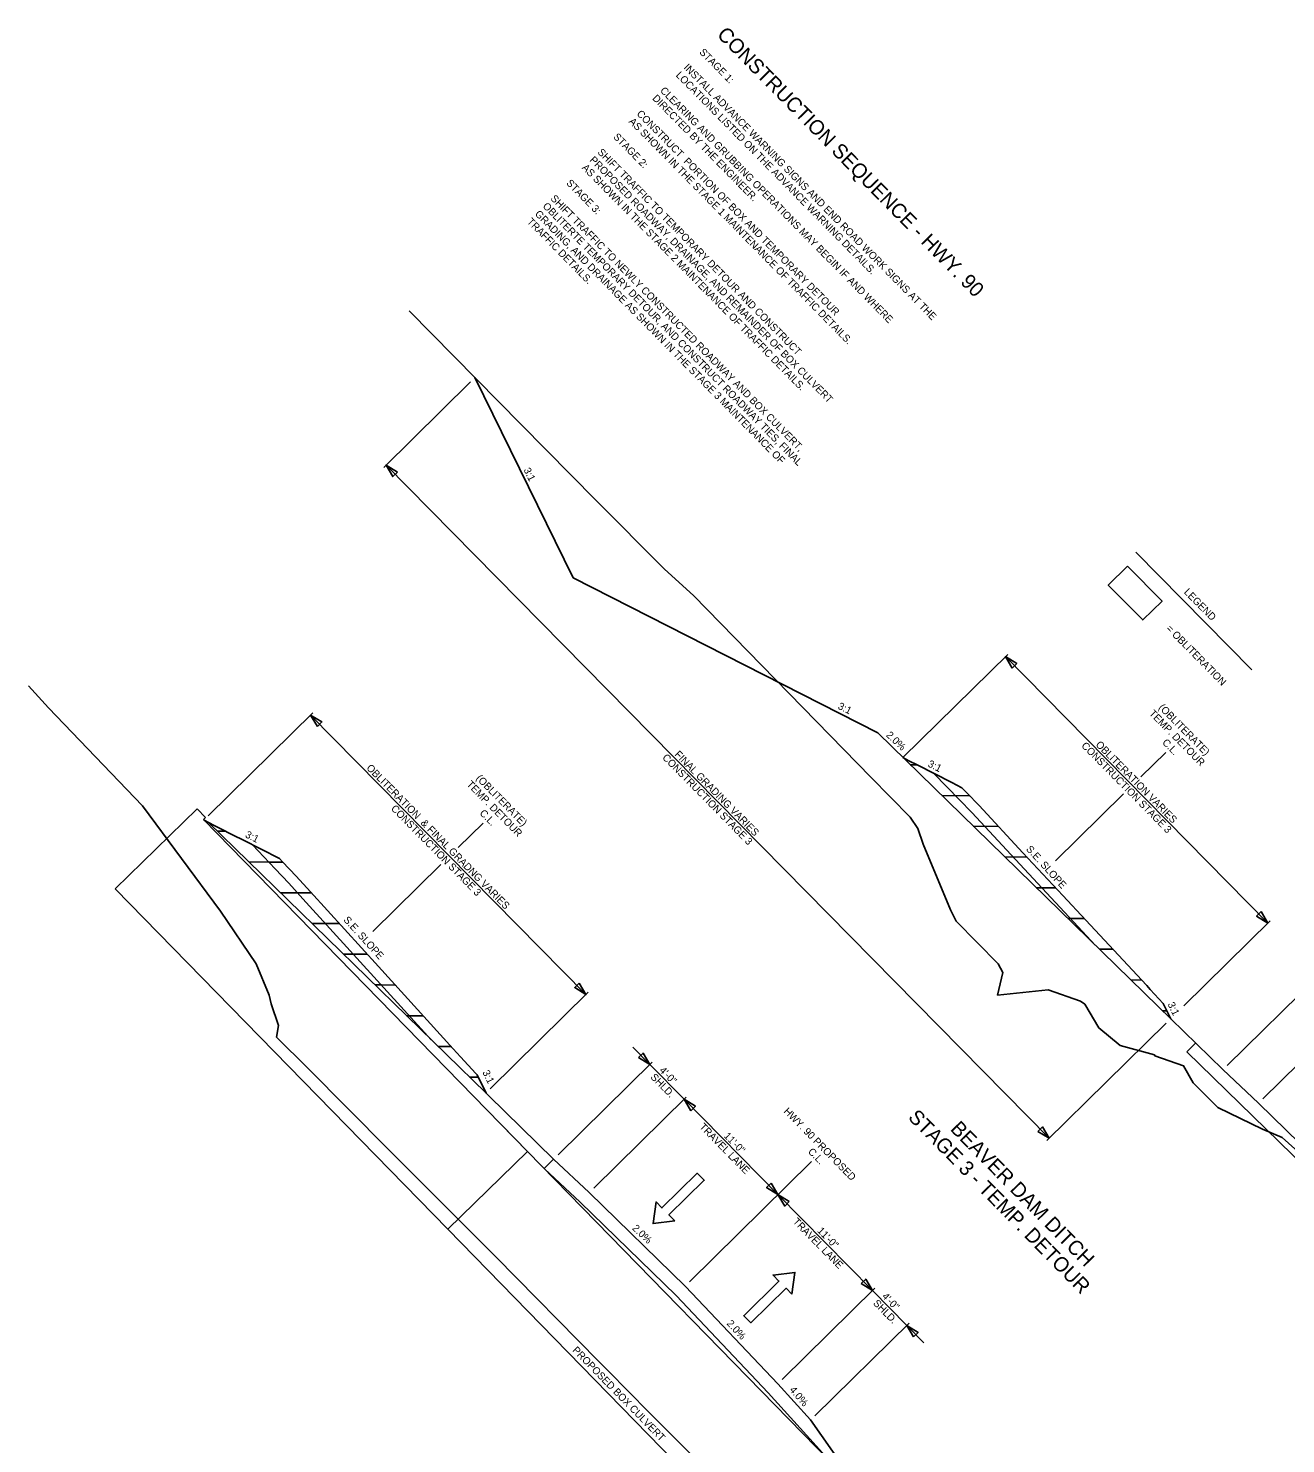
# Model space of a CAD drawing. Extents: x 1660305 to 1660468, y 670370 to 670550.
# Drawn here: x 1660305.5 to 1660408.5, y 670434.3 to 670550.3 of the extents above; entities that cross this region are included whole.
import ezdxf

# ---------------------------------------------------------------- set-up
doc = ezdxf.new("R2010")
doc.units = 0
for name, color, linetype in [('Default', 7, 'Continuous'), ('R_Annotation', 7, 'Continuous'), ('R_Axis', 7, 'Continuous'), ('R_Dimension', 7, 'Continuous'), ('R_Exist Surface', 7, 'Continuous'), ('R_Fin Surface', 7, 'Continuous'), ('R_Horz Alg', 7, 'Continuous'), ('R_MOT', 7, 'Continuous')]:
    doc.layers.add(name, color=color, linetype=linetype)

msp = doc.modelspace()

# ---------------------------------------------------------------- linework, layer by layer
at = {"layer": 'Default'}
for points in [[(1660358.47, 670452.53), (1660356.68, 670452.31), (1660356.92, 670454.09), (1660357.4, 670453.6), (1660360.29, 670456.44), (1660360.87, 670455.86), (1660357.98, 670453.02)], [(1660368.05, 670446.53), (1660368.29, 670448.31), (1660366.51, 670448.09), (1660366.99, 670447.6), (1660364.11, 670444.76), (1660364.68, 670444.18), (1660367.57, 670447.02)]]:
    msp.add_lwpolyline(points, close=True, dxfattribs=at)
at = {"layer": 'R_Annotation'}
msp.add_line((1660396.23, 670507.34), (1660405.73, 670497.69), dxfattribs=at)
at = {"layer": 'R_Axis'}
msp.add_lwpolyline([(1660395.55, 670506.2), (1660398.37, 670503.33), (1660396.79, 670501.78), (1660393.97, 670504.64)], close=True, dxfattribs=at)
at = {"layer": 'R_Dimension'}
for p, q in [((1660341.73, 670521.29), (1660334.61, 670514.28)), ((1660334.8, 670514.47), (1660389.12, 670459.3)), ((1660377.14, 670490.51), (1660385.73, 670498.96)), ((1660385.54, 670498.78), (1660407.04, 670476.94)), ((1660320.24, 670485.73), (1660328.81, 670494.18)), ((1660328.62, 670493.99), (1660351.18, 670471.08)), ((1660400.16, 670470.17), (1660407.23, 670477.13)), ((1660403.71, 670465.28), (1660411.42, 670472.87)), ((1660343.34, 670463.36), (1660351.37, 670471.27)), ((1660406.63, 670462.54), (1660414.22, 670470.02)), ((1660398.72, 670468.75), (1660388.93, 670459.11)), ((1660356.41, 670465.35), (1660355.01, 670466.77)), ((1660348.89, 670457.95), (1660356.6, 670465.53)), ((1660359.22, 670462.5), (1660356.41, 670465.35)), ((1660351.81, 670455.21), (1660359.4, 670462.68)), ((1660351.81, 670455.21), (1660359.4, 670462.68)), ((1660359.22, 670462.5), (1660366.9, 670454.69)), ((1660374.65, 670446.82), (1660366.9, 670454.69)), ((1660367.25, 670439.53), (1660374.84, 670447.01)), ((1660374.65, 670446.82), (1660377.46, 670443.97)), ((1660369.94, 670436.57), (1660377.65, 670444.16)), ((1660377.46, 670443.97), (1660378.86, 670442.55))]:
    msp.add_line(p, q, dxfattribs=at)
for points in [[(1660335.73, 670513.9), (1660334.8, 670514.47), (1660335.35, 670513.53)], [(1660386.09, 670497.84), (1660385.54, 670498.78), (1660386.47, 670498.21)], [(1660329.18, 670493.05), (1660328.62, 670493.99), (1660329.55, 670493.42)], [(1660406.49, 670477.88), (1660407.04, 670476.94), (1660406.11, 670477.51)], [(1660350.63, 670472.02), (1660351.18, 670471.08), (1660350.26, 670471.65)], [(1660355.48, 670465.92), (1660356.41, 670465.35), (1660355.86, 670466.29)], [(1660359.77, 670461.56), (1660359.22, 670462.5), (1660360.14, 670461.93)], [(1660388.19, 670459.87), (1660389.12, 670459.3), (1660388.57, 670460.24)], [(1660366.35, 670455.63), (1660366.9, 670454.69), (1660365.97, 670455.26)], [(1660367.83, 670454.12), (1660366.9, 670454.69), (1660367.46, 670453.75)], [(1660373.72, 670447.39), (1660374.65, 670446.82), (1660374.1, 670447.76)], [(1660378.01, 670443.03), (1660377.46, 670443.97), (1660378.39, 670443.4)]]:
    msp.add_lwpolyline(points, close=True, dxfattribs=at)
at = {"layer": 'R_Exist Surface'}
for points in [[(1660336.7, 670527.11), (1660345.87, 670517.8), (1660351.98, 670511.6), (1660357.62, 670505.95), (1660359.99, 670503.8), (1660374.51, 670488.91), (1660377.74, 670485.63), (1660378.37, 670484.7), (1660378.81, 670483.4), (1660381.03, 670478.03), (1660381.5, 670477.1), (1660384.96, 670473.59), (1660385.33, 670472.88), (1660384.9, 670471.04), (1660389.03, 670471.46), (1660391.7, 670470.54), (1660392.05, 670470.29), (1660393.2, 670468.35), (1660394.93, 670466.91), (1660397.74, 670466.13), (1660397.79, 670466.07), (1660400.14, 670465.23), (1660400.93, 670463.86), (1660402.93, 670461.82), (1660406.6, 670460.04), (1660408.22, 670459.37), (1660414.98, 670453.31)], [(1660305.5, 670496.38), (1660307.16, 670494.59), (1660314.86, 670486.54), (1660321.25, 670477.93), (1660324.15, 670473.59), (1660325.23, 670471.03), (1660325.39, 670470.33), (1660326, 670468.55), (1660325.84, 670467.6), (1660328.38, 670465.04), (1660334.97, 670458.4), (1660339.75, 670453.64), (1660343.8, 670449.59), (1660352.23, 670441.02), (1660352.99, 670440.24), (1660356.34, 670436.86), (1660362.34, 670430.84)]]:
    msp.add_lwpolyline(points, dxfattribs=at)
at = {"layer": 'R_Fin Surface'}
for points in [[(1660342.08, 670521.64), (1660350.13, 670505.24), (1660375.08, 670492.52), (1660398.05, 670470.11), (1660399.08, 670469.1)], [(1660319.89, 670485.37), (1660320.26, 670485.19), (1660342.99, 670463.01)]]:
    msp.add_lwpolyline(points, dxfattribs=at)
at = {"layer": 'R_Horz Alg'}
for p, q in [((1660396.64, 670488.93), (1660398.67, 670490.93)), ((1660389.65, 670482.04), (1660395.21, 670487.53)), ((1660340.72, 670483.13), (1660342.75, 670485.13)), ((1660333.73, 670476.25), (1660339.29, 670481.73)), ((1660359.66, 670447.55), (1660369.65, 670457.39))]:
    msp.add_line(p, q, dxfattribs=at)
at = {"layer": 'R_MOT'}
for p, q in [((1660377.74, 670489.92), (1660378.29, 670489.92)), ((1660381.77, 670487.04), (1660379.67, 670489.21)), ((1660380.33, 670487.4), (1660382.6, 670487.38)), ((1660382.78, 670486), (1660381.77, 670487.04)), ((1660319.32, 670486.31), (1660312.61, 670479.76)), ((1660319.32, 670486.31), (1660320.02, 670485.6)), ((1660386.36, 670482.15), (1660382.78, 670486)), ((1660320.02, 670485.6), (1660319.84, 670485.42)), ((1660319.84, 670485.42), (1660346.39, 670458.23)), ((1660320.99, 670484.47), (1660321.67, 670484.47)), ((1660382.91, 670484.88), (1660384.97, 670484.86)), ((1660385.49, 670482.36), (1660387.31, 670482.35)), ((1660389.63, 670478.64), (1660386.36, 670482.15)), ((1660323.57, 670481.95), (1660325.2, 670481.94)), ((1660325.19, 670481.94), (1660326.34, 670481.93)), ((1660388.07, 670479.84), (1660389.66, 670479.83)), ((1660312.61, 670479.76), (1660339.86, 670451.86)), ((1660326.15, 670479.43), (1660327.54, 670479.42)), ((1660327.54, 670479.42), (1660328.67, 670479.41)), ((1660391.51, 670476.62), (1660389.63, 670478.64)), ((1660328.74, 670476.91), (1660329.83, 670476.9)), ((1660329.83, 670476.91), (1660330.97, 670476.9)), ((1660390.66, 670477.32), (1660392.01, 670477.31)), ((1660392.89, 670475.14), (1660391.51, 670476.62)), ((1660331.32, 670474.39), (1660332.13, 670474.39)), ((1660332.12, 670474.39), (1660333.26, 670474.38)), ((1660393.24, 670474.8), (1660394.36, 670474.79)), ((1660333.9, 670471.87), (1660334.42, 670471.87)), ((1660334.42, 670471.87), (1660335.55, 670471.86)), ((1660395.82, 670472.28), (1660396.71, 670472.27)), ((1660398.41, 670469.76), (1660398.76, 670469.76)), ((1660336.48, 670469.35), (1660336.71, 670469.35)), ((1660336.71, 670469.35), (1660337.84, 670469.34)), ((1660400.41, 670466.4), (1660401.12, 670467.11)), ((1660339.06, 670466.83), (1660340.14, 670466.83)), ((1660341.65, 670464.31), (1660342.35, 670464.31)), ((1660344.26, 670460.41), (1660347.52, 670457.07)), ((1660346.39, 670458.23), (1660339.86, 670451.86)), ((1660374.3, 670429.64), (1660346.39, 670458.23)), ((1660348.53, 670457.59), (1660347.76, 670456.83)), ((1660339.86, 670451.86), (1660368.5, 670422.52))]:
    msp.add_line(p, q, dxfattribs=at)
for points in [[(1660377.14, 670490.51), (1660377.63, 670490.25), (1660378.3, 670489.91), (1660381.14, 670488.45), (1660381.98, 670488.02), (1660382.37, 670487.62), (1660383.38, 670486.58), (1660386.97, 670482.71), (1660390.24, 670479.21), (1660392.12, 670477.18), (1660397.11, 670471.85), (1660397.13, 670471.82), (1660397.41, 670471.51), (1660398.46, 670470.35), (1660398.58, 670470.12), (1660399.08, 670469.1)], [(1660319.88, 670485.38), (1660322.33, 670484.13), (1660323.07, 670483.75), (1660326.06, 670482.23), (1660326.31, 670481.96), (1660327.44, 670480.78), (1660328.6, 670479.49), (1660334.17, 670473.37), (1660340.31, 670466.64), (1660340.91, 670465.97), (1660342.15, 670464.61), (1660342.26, 670464.49), (1660342.99, 670463.01)], [(1660323.85, 670483.36), (1660325.71, 670481.39), (1660326.83, 670480.21), (1660327.98, 670478.93), (1660338.51, 670467.37)], [(1660323.85, 670483.36), (1660325.71, 670481.39), (1660326.83, 670480.21), (1660327.98, 670478.93), (1660338.51, 670467.37)], [(1660399.08, 670469.1), (1660403.35, 670464.93), (1660406.27, 670462.19), (1660414.15, 670454.51), (1660421.71, 670446.52), (1660424.4, 670443.56), (1660428.72, 670437.41), (1660429.07, 670436.92), (1660436.55, 670421.66)], [(1660400.41, 670466.4), (1660413.38, 670453.75), (1660428.39, 670437.88)], [(1660342.99, 670463.01), (1660343.23, 670462.77), (1660348.53, 670457.59), (1660351.45, 670454.86), (1660359.33, 670447.17), (1660366.89, 670439.18), (1660369.58, 670436.22), (1660373.9, 670430.07), (1660373.96, 670429.99)], [(1660347.76, 670456.83), (1660347.79, 670456.81), (1660350.71, 670454.07), (1660358.56, 670446.41), (1660366.1, 670438.44), (1660371.35, 670432.66)]]:
    msp.add_lwpolyline(points, dxfattribs=at)

# ---------------------------------------------------------------- texts
at = {"layer": 'R_Annotation'}
for s, height, rotation, p in [('CONSTRUCTION SEQUENCE - HWY. 90', 1.2, 314.5576, (1660361.84, 670549.68)), ('STAGE 1: ', 0.6, 314.5576, (1660360.42, 670548.27)), ('INSTALL ADVANCE WARNING SIGNS AND END ROAD WORK SIGNS AT THE ', 0.6, 314.5576, (1660359.14, 670547.01)), ('LOCATIONS LISTED ON THE ADVANCE WARNING DETAILS. ', 0.6, 314.5576, (1660358.5, 670546.38)), ('DIRECTED BY THE ENGINEER.', 0.6, 314.5576, (1660356.57, 670544.49)), ('CLEARING AND GRUBBING OPERATIONS MAY BEGIN IF AND WHERE ', 0.6, 314.5576, (1660357.21, 670545.12)), ('AS SHOWN IN THE STAGE 1 MAINTENANCE OF TRAFFIC DETAILS.', 0.6, 314.5576, (1660354.65, 670542.59)), ('CONSTRUCT  PORTION OF BOX AND TEMPORARY DETOUR', 0.6, 314.5576, (1660355.29, 670543.22)), ('STAGE 2:', 0.6, 314.5576, (1660353.37, 670541.33)), ('SHIFT TRAFFIC TO TEMPORARY DETOUR AND CONSTRUCT ', 0.6, 314.5576, (1660352.08, 670540.07)), ('AS SHOWN IN THE STAGE 2 MAINTENANCE OF TRAFFIC DETAILS.', 0.6, 314.5576, (1660350.8, 670538.8)), ('PROPOSED ROADWAY, DRAINAGE, AND REMAINDER OF BOX CULVERT', 0.6, 314.5576, (1660351.44, 670539.43)), ('STAGE 3:', 0.6, 314.5576, (1660349.52, 670537.54)), ('OBLITERTE TEMPORARY DETOUR, AND CONSTRUCT ROADWAY TIES, FINAL', 0.6, 314.5576, (1660347.59, 670535.65)), ('SHIFT TRAFFIC TO NEWLY CONSTRUCTED ROADWAY AND BOX CULVERT, ', 0.6, 314.5576, (1660348.23, 670536.28)), ('TRAFFIC DETAILS.', 0.6, 314.5576, (1660346.31, 670534.38)), ('GRADING, AND DRAINAGE AS SHOWN IN THE STAGE 3 MAINTENANCE OF ', 0.6, 314.5576, (1660346.95, 670535.01)), ('3:1', 0.6, 296.1227, (1660346.05, 670514.09)), ('LEGEND', 0.6, 314.5565, (1660400.12, 670504.02)), ('= OBLITERATION', 0.6, 314.5565, (1660398.66, 670501.03)), ('3:1', 0.6, 333.3952, (1660371.76, 670494.53)), ('TEMP. DETOUR', 0.6, 314.5576, (1660397.27, 670494.07)), ('(OBLITERATE)', 0.6, 314.5576, (1660398.04, 670494.56)), ('2.0%', 0.6, 316.5576, (1660375.72, 670492.29)), ('CONSTRUCTION STAGE 3', 0.6, 314.5576, (1660391.72, 670491.43)), ('OBLITERATION VARIES', 0.6, 314.5576, (1660392.89, 670491.52)), ('C.L.', 0.6, 314.5576, (1660398.34, 670491.69)), ('CONSTRUCTION STAGE 3', 0.6, 314.5576, (1660357.39, 670490.46)), ('FINAL GRADING VARIES', 0.6, 314.5576, (1660358.39, 670490.72)), ('3:1', 0.6, 333.3952, (1660379.13, 670489.8)), ('OBLITERATION  & FINAL GRADNG VARIES', 0.6, 314.5576, (1660333.15, 670489.61)), ('TEMP. DETOUR', 0.6, 314.5576, (1660341.35, 670488.27)), ('(OBLITERATE)', 0.6, 314.5576, (1660342.12, 670488.76)), ('CONSTRUCTION STAGE 3', 0.6, 314.5576, (1660335.16, 670486.28)), ('C.L.', 0.6, 314.5576, (1660342.42, 670485.9)), ('3:1', 0.6, 333.3952, (1660323.21, 670484)), ('S.E. SLOPE', 0.6, 312.322, (1660387.19, 670482.97)), ('S.E. SLOPE', 0.6, 312.322, (1660331.27, 670477.17)), ('3:1', 0.6, 295.7201, (1660398.81, 670470.3)), ('3:1', 0.6, 295.7201, (1660342.68, 670464.72)), ('4\'-0"', 0.6, 314.5576, (1660357.14, 670464.82)), ('SHLD.', 0.6, 314.5576, (1660356.42, 670464.27)), ('HWY. 90 PROPOSED', 0.6, 314.5576, (1660367.33, 670461.46)), ('STAGE 3 - TEMP. DETOUR', 1.2, 314.5226, (1660377.5, 670460.95)), ('TRAVEL LANE', 0.6, 314.5576, (1660360.42, 670460.2)), ('BEAVER DAM DITCH', 1.2, 314.5226, (1660380.96, 670460)), ('11\'-0"', 0.6, 314.5576, (1660362.43, 670459.45)), ('C.L.', 0.6, 314.5576, (1660369.32, 670458.16)), ('2.0%', 0.6, 316.5576, (1660354.92, 670451.87)), ('TRAVEL LANE', 0.6, 314.5576, (1660368.08, 670452.43)), ('11\'-0"', 0.6, 314.5576, (1660370.08, 670451.68)), ('4\'-0"', 0.6, 314.5576, (1660375.38, 670446.3)), ('SHLD.', 0.6, 314.5576, (1660374.66, 670445.74)), ('2.0%', 0.6, 312.5576, (1660362.67, 670444.09)), ('PROPOSED BOX CULVERT', 0.6, 314.3141, (1660350.02, 670441.89)), ('4.0%', 0.6, 310.5576, (1660367.81, 670438.66))]:
    msp.add_text(s, height=height, rotation=rotation, dxfattribs=at).set_placement(p)

doc.saveas('drawing.dxf')
